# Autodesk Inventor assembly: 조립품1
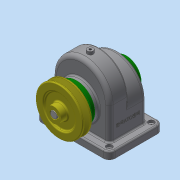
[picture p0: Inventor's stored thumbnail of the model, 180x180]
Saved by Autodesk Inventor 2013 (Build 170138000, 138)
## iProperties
Created: 2017-11
Part Number: 조립품1
Document SubType Name: Assembly
Designer: Administrator
Author: Administrator
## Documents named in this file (14)
- C:\Users\Administrator\Desktop\471107V1013\조립품1.iam
- C:\Users\Administrator\Desktop\471107V1013-김진기\부품11.ipt
- C:\Users\Administrator\Desktop\471107V1013\축.ipt
- C:\Users\Administrator\Desktop\471107V1013\키 - 5 x 5 x 18.ipt
- C:\Users\Administrator\Desktop\471107V1013\키 - 6 x 6 x 22.ipt
- C:\Users\Administrator\Desktop\471107V1013\베어링 6002.ipt
- C:\Users\Administrator\Desktop\471107V1013\앞커버.ipt
- C:\Users\Administrator\Desktop\471107V1013\오일 실 15 30 7.ipt
- C:\Users\Administrator\Desktop\471107V1013\뒤커버.ipt
- C:\Users\Administrator\Desktop\471107V1013\V-벨트풀리.ipt
- C:\Users\Administrator\Desktop\471107V1013\멈춤나사 - M4 x 10.ipt
- 멈춤나사 - M4 x 10.ipt
- C:\Users\Administrator\Desktop\471107V1013\스퍼기어.ipt
- C:\Users\Administrator\Desktop\471107V1013\볼트 M3 x 8.ipt
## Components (1 placed, 1 different names)
1. V-벨트풀리:1 — 각도:4
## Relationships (1: Angle 1)
- 각도:4 [Angle]: V-벨트풀리:1
